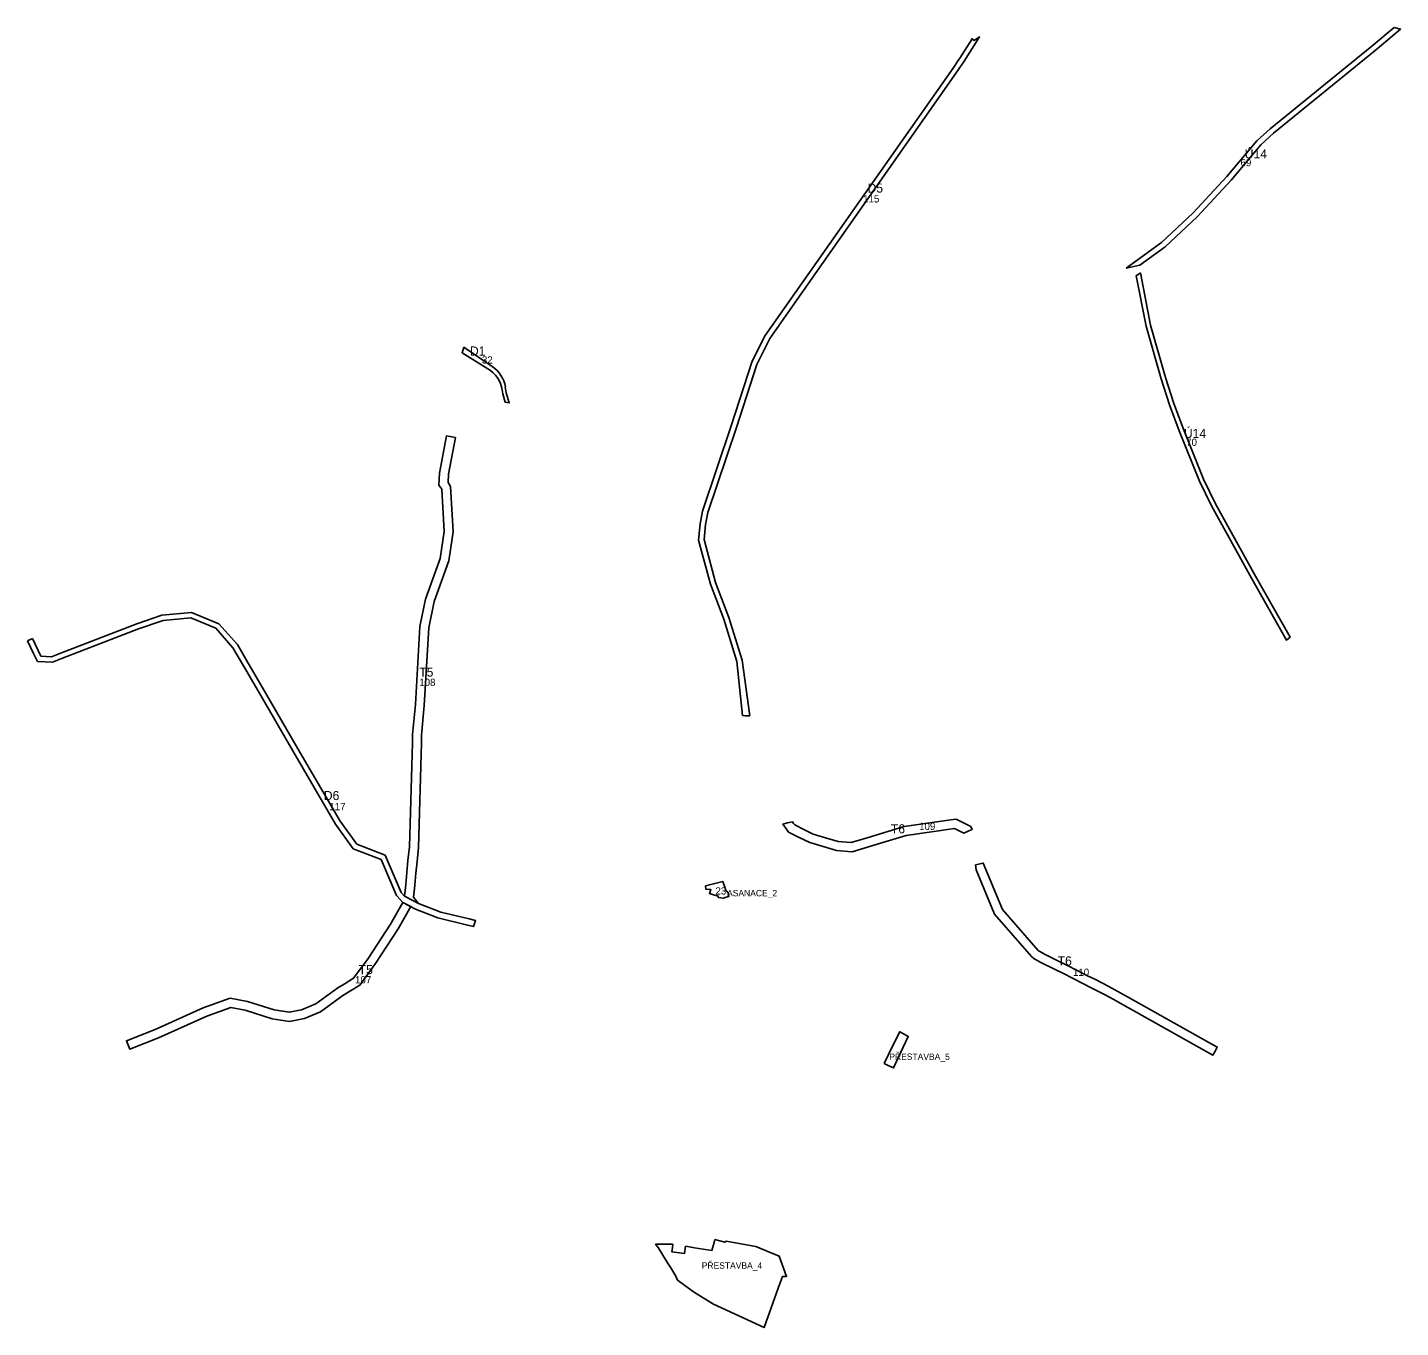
# Model space of a CAD drawing. Extents: x -521621 to -516857, y -1190025 to -1185894.
# Drawn here: x -519434 to -517922, y -1187326 to -1185894 of the extents above; entities that cross this region are included whole.
import ezdxf

# ---------------------------------------------------------------- set-up
doc = ezdxf.new("R2010")
doc.units = 0
for name, color, linetype in [('A_id', 7, 'Continuous'), ('asanace_n', 7, 'Continuous'), ('prestavba_n', 7, 'Continuous'), ('VPO_id', 7, 'Continuous'), ('VPO_n', 7, 'Continuous'), ('VPS_id', 7, 'Continuous'), ('VPS_n', 7, 'Continuous')]:
    doc.layers.add(name, color=color, linetype=linetype)

msp = doc.modelspace()

# ---------------------------------------------------------------- linework, layer by layer
at = {"layer": 'asanace_n'}
msp.add_lwpolyline([(-518687.6, -1186839.4), (-518687.5, -1186842.8), (-518681.8, -1186843.4), (-518683.5, -1186847.6), (-518680, -1186848.7), (-518673.8, -1186850.6), (-518673.8, -1186852.1), (-518668, -1186852.7), (-518665, -1186851.9), (-518662, -1186851.2), (-518663.2, -1186846.4), (-518665.3, -1186844.4), (-518666.9, -1186839.5), (-518668.5, -1186834.7), (-518687.6, -1186839.4)], dxfattribs=at)
at = {"layer": 'prestavba_n'}
for points in [[(-518491.1, -1187034.9), (-518485.9, -1187037.4), (-518480.7, -1187039.7), (-518464.5, -1187005.1), (-518469.1, -1187002.5), (-518473.9, -1186999.9), (-518481.7, -1187015.8), (-518491.1, -1187034.9)], [(-518678.3, -1187232.1), (-518680.6, -1187240.7), (-518699.7, -1187237.7), (-518703.4, -1187237.1), (-518709.7, -1187236.1), (-518710.8, -1187244), (-518725, -1187242.2), (-518724.2, -1187237.6), (-518723.6, -1187234), (-518724.9, -1187233.8), (-518742.7, -1187233.9), (-518740, -1187237.6), (-518729.6, -1187254.3), (-518726.1, -1187259.9), (-518720.3, -1187269.1), (-518718.5, -1187273.4), (-518699.8, -1187287), (-518678.9, -1187300), (-518623.2, -1187325.6), (-518607.6, -1187282.1), (-518604.1, -1187272.3), (-518603, -1187269.4), (-518598.4, -1187269.2), (-518606.7, -1187246.9), (-518632.3, -1187236.3), (-518664.9, -1187230.6), (-518666.6, -1187231.7), (-518677.4, -1187228.8), (-518678.3, -1187232.1)]]:
    msp.add_lwpolyline(points, dxfattribs=at)
at = {"layer": 'VPO_n'}
for points in [[(-518224.3, -1186159.4), (-518185.4, -1186131.2), (-518150.7, -1186098.5), (-518113.5, -1186058.4), (-518080.5, -1186019.2), (-518066, -1186005.9), (-517953.9, -1185915), (-517929.5, -1185894.3), (-517922.3, -1185896.1), (-517950.1, -1185919.7), (-518062.1, -1186010.5), (-518076.2, -1186023.4), (-518109, -1186062.4), (-518146.4, -1186102.7), (-518181.5, -1186135.9), (-518209.5, -1186156.1)], [(-518208.8, -1186164.4), (-518197.5, -1186221.9), (-518181.1, -1186279.8), (-518171.9, -1186308.2), (-518161.3, -1186336.6), (-518139.2, -1186391.6), (-518126.2, -1186418.6), (-518082.2, -1186498.2), (-518043.9, -1186565.7), (-518048, -1186568.7), (-518086.6, -1186500.7), (-518130.6, -1186420.9), (-518143.7, -1186393.7), (-518166, -1186338.5), (-518176.7, -1186309.9), (-518185.9, -1186281.2), (-518202.4, -1186223.1), (-518213.3, -1186167.7)]]:
    msp.add_lwpolyline(points, close=True, dxfattribs=at)
at = {"layer": 'VPS_n'}
for points in [[(-518408.8, -1185929.5), (-518407.8, -1185928), (-518394.2, -1185906.7), (-518391.7, -1185908.5), (-518385.9, -1185904.8), (-518402.8, -1185931.3)], [(-518636.5, -1186261.5), (-518622.2, -1186233.6), (-518414.9, -1185939)], [(-518409.2, -1185940.6), (-518617, -1186236.6), (-518631.4, -1186265.3)], [(-518414.9, -1185939), (-518408.8, -1185929.5)], [(-518402.8, -1185931.3), (-518409.2, -1185940.6)], [(-518953.9, -1186246.2), (-518955.8, -1186252.5), (-518927.4, -1186270)], [(-518922.6, -1186267.6), (-518953.9, -1186246.2)], [(-518638.9, -1186652.2), (-518644, -1186652.1), (-518647, -1186651.6), (-518653.3, -1186592.2), (-518667.6, -1186545.9), (-518682.3, -1186507.3), (-518695.4, -1186458.6), (-518693.7, -1186440.7), (-518690.9, -1186426.8), (-518659.5, -1186333), (-518636.5, -1186261.5)], [(-518631.4, -1186265.3), (-518653.7, -1186334.8), (-518685.1, -1186428.3), (-518687.8, -1186441.6), (-518689.3, -1186458.1), (-518676.6, -1186505.5), (-518661.9, -1186544), (-518647.4, -1186591), (-518638.9, -1186652.2)], [(-518911.7, -1186293.4), (-518911, -1186297.5), (-518908.2, -1186306.9), (-518903.9, -1186307.5), (-518907.1, -1186296.6), (-518908.2, -1186290.1)], [(-519015.4, -1186811.5), (-519013.9, -1186796.5), (-519010.6, -1186681.7), (-519010.4, -1186672.8), (-519007.3, -1186639.8), (-519002.2, -1186553.8), (-518996.1, -1186523.7), (-518980.1, -1186479), (-518975.6, -1186449.1), (-518978.3, -1186402.7), (-518981.4, -1186398.1), (-518980.6, -1186385), (-518973, -1186343.9), (-518963.1, -1186345.8), (-518970.7, -1186386.2), (-518971.2, -1186395.4), (-518968.5, -1186399.5), (-518965.6, -1186449.6), (-518970.4, -1186481.5), (-518986.4, -1186526.4), (-518992.3, -1186555.1), (-518997.4, -1186640.6), (-519000.4, -1186673.4), (-519000.6, -1186682), (-519004, -1186797.1), (-519005.4, -1186812.4), (-519006.7, -1186825.4), (-519008, -1186838.6), (-519008.6, -1186845.6), (-519009.2, -1186851.7), (-519003.8, -1186858.7), (-519019.2, -1186850.6), (-519018.6, -1186844.6), (-519017.9, -1186837.7), (-519016.7, -1186824.5), (-519015.4, -1186811.5)], [(-519314.2, -1186550.8), (-519286.5, -1186541.3)], [(-519286.5, -1186541.3), (-519253.7, -1186538.2)], [(-519254.6, -1186544.3), (-519285.2, -1186547.2)], [(-519227.2, -1186555.7), (-519254.6, -1186544.3)], [(-519253.7, -1186538.2), (-519223.6, -1186550.7)], [(-519396.9, -1186582.8), (-519314.2, -1186550.8)], [(-519312.1, -1186556.4), (-519395.9, -1186588.8)], [(-519285.2, -1186547.2), (-519312.1, -1186556.4)], [(-519208.2, -1186577.3), (-519227.2, -1186555.7)], [(-519223.6, -1186550.7), (-519203.3, -1186573.7)], [(-519434.5, -1186569.6), (-519429.1, -1186567)], [(-519427.8, -1186583.6), (-519434.5, -1186569.6)], [(-519429.1, -1186567), (-519419.7, -1186586.6)], [(-519203.3, -1186573.7), (-519191.4, -1186594.2)], [(-519423.5, -1186592.5), (-519427.8, -1186583.6)], [(-519419.7, -1186586.6), (-519408, -1186587.1)], [(-519408, -1186587.1), (-519396.9, -1186582.8)], [(-519395.9, -1186588.8), (-519407, -1186593.1)], [(-519196.6, -1186597.2), (-519208.2, -1186577.3)], [(-519407, -1186593.1), (-519423.5, -1186592.5)], [(-519180.2, -1186625.3), (-519196.6, -1186597.2)], [(-519191.4, -1186594.2), (-519175, -1186622.3)], [(-519142.2, -1186690.6), (-519180.2, -1186625.3)], [(-519175, -1186622.3), (-519137, -1186687.6), (-519090.1, -1186768.1)], [(-519095.1, -1186771.4), (-519142.2, -1186690.6)], [(-519075.6, -1186798.4), (-519095.1, -1186771.4)], [(-519090.1, -1186768.1), (-519071.8, -1186793.4)], [(-518573, -1186791.7), (-518584.6, -1186785.9), (-518596.2, -1186780.1), (-518599.3, -1186775.7), (-518602.5, -1186771.3), (-518597.3, -1186770), (-518592, -1186768.7), (-518590.7, -1186770.5), (-518589.5, -1186772.2), (-518579.4, -1186777.3), (-518569.3, -1186782.3), (-518555.5, -1186786.4), (-518541.7, -1186790.6), (-518527.2, -1186791.6), (-518509.8, -1186786.4)], [(-518509.8, -1186786.4), (-518468.8, -1186774.1), (-518414.9, -1186766.3), (-518411.8, -1186765.9), (-518395.6, -1186774), (-518394.1, -1186777.2), (-518397.7, -1186778.8), (-518403.2, -1186781.3), (-518413.4, -1186776.2), (-518466.7, -1186783.9), (-518499.7, -1186793.8)], [(-519045, -1186810.3), (-519075.6, -1186798.4)], [(-519071.8, -1186793.4), (-519040.5, -1186805.6)], [(-518499.7, -1186793.8), (-518526.1, -1186801.7), (-518543.5, -1186800.4), (-518573, -1186791.7)], [(-519028, -1186850.1), (-519045, -1186810.3)], [(-519040.5, -1186805.6), (-519022.9, -1186846.8)], [(-519022.9, -1186846.8), (-519019.2, -1186850.6)], [(-519021, -1186857.6), (-519028, -1186850.1)], [(-519007, -1186864.9), (-519021, -1186857.6)], [(-519019.2, -1186850.6), (-519003.8, -1186858.7)], [(-519003.8, -1186858.7), (-518979.2, -1186868.2), (-518948, -1186875.8), (-518940.9, -1186877.6), (-518943.1, -1186884.1), (-518951.3, -1186882.1), (-518982.5, -1186874.5), (-519007, -1186864.9)]]:
    msp.add_lwpolyline(points, dxfattribs=at)
for points in [[(-518369.3, -1186870.6), (-518389.7, -1186821.6), (-518390.4, -1186816.3), (-518381.9, -1186814.2), (-518360.7, -1186865.2), (-518321.3, -1186910.5), (-518314.4, -1186914.4), (-518298.2, -1186922.5), (-518289.9, -1186926.7), (-518266.9, -1186938.3), (-518259.1, -1186942.2), (-518243.5, -1186950.1), (-518233.8, -1186955.5), (-518223, -1186961.5), (-518124.1, -1187016.9), (-518126.5, -1187021.3), (-518128.9, -1187025.6), (-518227.9, -1186970.3), (-518238.7, -1186964.2), (-518248.2, -1186958.9), (-518263.6, -1186951.1), (-518271.4, -1186947.2), (-518294.4, -1186935.6), (-518302.7, -1186931.4), (-518319.1, -1186923.2), (-518326.2, -1186919.2), (-518328.9, -1186917)], [(-519240.8, -1186973.6), (-519211.2, -1186963.1), (-519192.2, -1186966.6), (-519162.7, -1186975.8), (-519146.1, -1186978.5), (-519132.5, -1186975.8), (-519116.9, -1186969.1), (-519092.6, -1186951.6), (-519085.8, -1186947.5), (-519075.4, -1186941.1), (-519059.4, -1186919.2), (-519034.7, -1186881.5), (-519021, -1186857.6), (-519012.1, -1186862.2), (-519026.2, -1186886.7), (-519051.2, -1186924.9), (-519068.5, -1186948.7), (-519087.1, -1186960), (-519111.9, -1186977.9), (-519129.5, -1186985.4), (-519145.9, -1186988.7), (-519165, -1186985.6), (-519194.7, -1186976.3), (-519210.4, -1186973.4), (-519237, -1186982.9), (-519290, -1187006.8), (-519321.9, -1187019.1), (-519325.5, -1187009.8), (-519293.9, -1186997.6)]]:
    msp.add_lwpolyline(points, close=True, dxfattribs=at)
for centre, end in [((-518945.2, -1186299), 58.3971), ((-518941.7, -1186295.7), 55.7376)]:
    msp.add_arc(centre, 34, 9.5068, end, dxfattribs=at)

# ---------------------------------------------------------------- texts
at = {"layer": 'A_id'}
msp.add_text('23', height=8, dxfattribs=at).set_placement((-518676.8, -1186848.9))
at = {"layer": 'asanace_n'}
msp.add_text('ASANACE_2', height=7, dxfattribs=at).set_placement((-518664, -1186850.8))
at = {"layer": 'prestavba_n'}
for s, p in [('PŘESTAVBA_5', (-518485.3, -1187030.9)), ('PŘESTAVBA_4', (-518691.9, -1187260.8))]:
    msp.add_text(s, height=7, dxfattribs=at).set_placement(p)
at = {"layer": 'VPO_id'}
for s, p in [('69', (-518098.5, -1186047.1)), ('70', (-518158.4, -1186354.9))]:
    msp.add_text(s, height=8, dxfattribs=at).set_placement(p)
at = {"layer": 'VPO_n'}
for p in [(-518093.9, -1186038.5), (-518160.9, -1186346.2)]:
    msp.add_text('Ú14', height=10, dxfattribs=at).set_placement(p)
at = {"layer": 'VPS_id'}
for s, p in [('115', (-518514.2, -1186087)), ('32', (-518934, -1186264.3)), ('108', (-519003, -1186619.3)), ('117', (-519102, -1186756)), ('109', (-518452.5, -1186777.8)), ('107', (-519073.7, -1186946.7)), ('110', (-518283.1, -1186938.4))]:
    msp.add_text(s, height=8, dxfattribs=at).set_placement(p)
at = {"layer": 'VPS_n'}
for s, p in [('D5', (-518509.3, -1186076.1)), ('D1', (-518947.2, -1186255.5)), ('T5', (-519003, -1186609)), ('D6', (-519108.1, -1186744.9)), ('T6', (-518483.6, -1186781.5)), ('T6', (-518299.9, -1186926.9)), ('T5', (-519069.7, -1186936.6))]:
    msp.add_text(s, height=10, dxfattribs=at).set_placement(p)

doc.saveas('drawing.dxf')
